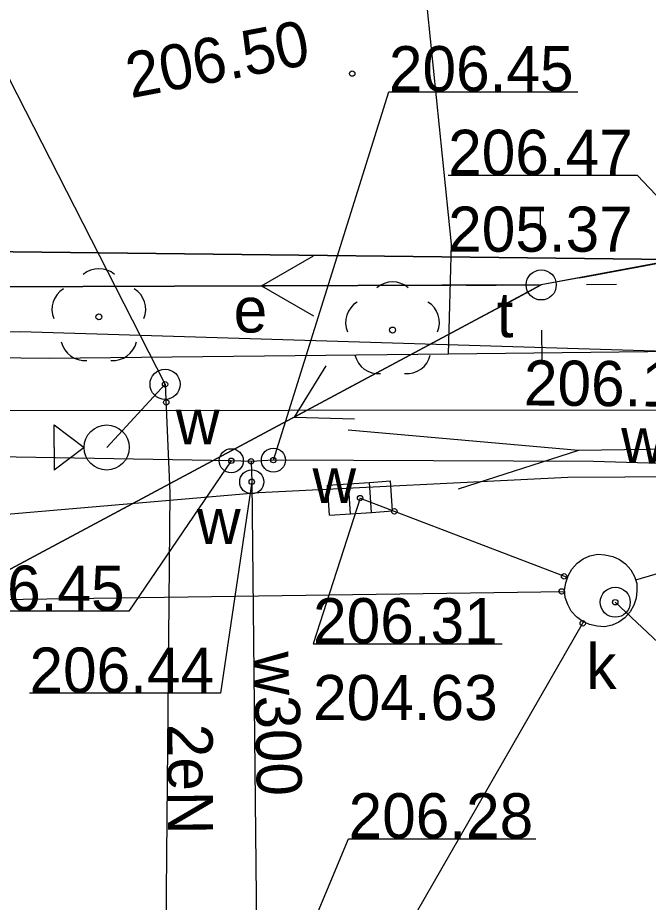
# Model space of a CAD drawing. Extents: x 6512606 to 6513347, y 6022524 to 6022728.
# Drawn here: x 6512773.39 to 6512783.87, y 6022679.43 to 6022694.12 of the extents above; entities that cross this region are included whole.
import ezdxf

# ---------------------------------------------------------------- set-up
doc = ezdxf.new("R2010")
doc.units = 0
for name, color, linetype in [('218-kontur użytku gruntowego', 7, 'Continuous'), ('219-działka ewidencyjna', 7, 'Continuous'), ('4', 7, 'Continuous'), ('chodnik (powierzchnia)', 7, 'Continuous'), ('Default', 7, 'Continuous'), ('drzewo liściaste (punkt)', 7, 'Continuous'), ('inna obudowa przewodu - sieć elektroenergetyczna (linia)', 7, 'Continuous'), ('komora podziemna - przewód kanalizacyjny (powierzchnia)', 7, 'Continuous'), ('kratka ściekowa (punkt)', 7, 'Continuous'), ('krawężnik (linia)', 7, 'Continuous'), ('latarnia na słupie lub maszcie (punkt)', 7, 'Continuous'), ('przewód elektroenergetyczny (linia)', 7, 'Continuous'), ('przewód elektroenergetyczny (linia)-Atr1', 7, 'Continuous'), ('przewód elektroenergetyczny niskiego napięcia (linia)', 7, 'Continuous'), ('przewód elektroenergetyczny niskiego napięcia (linia) - symbol', 7, 'Continuous'), ('przewód gazowy (linia)', 7, 'Continuous'), ('przewód kanalizacyjny (linia)', 7, 'Continuous'), ('przewód telekomunikacyjny (linia)', 7, 'Continuous'), ('przewód wodociągowy (linia)', 7, 'Continuous'), ('przewód wodociągowy (linia)-Atr1', 7, 'Continuous'), ('punkt o określonej wysokości (sieć elektroenergetyczna)', 7, 'Continuous'), ('punkt o określonej wysokości (sieć elektroenergetyczna)-Atr2', 7, 'Continuous'), ('punkt o określonej wysokości (sieć kanalizacyjna)', 7, 'Continuous'), ('punkt o określonej wysokości (sieć kanalizacyjna)-Atr2', 7, 'Continuous'), ('punkt o określonej wysokości (sieć kanalizacyjna)-Atr3', 7, 'Continuous'), ('punkt o określonej wysokości (sieć telekomunikacyjna)-Atr2', 7, 'Continuous'), ('punkt o określonej wysokości (sieć telekomunikacyjna)-Atr3', 7, 'Continuous'), ('punkt o określonej wysokości (sieć wodociągowa)', 7, 'Continuous'), ('punkt o określonej wysokości (sieć wodociągowa)-Atr2', 7, 'Continuous'), ('punkt wysokościowy sztuczny', 7, 'Continuous'), ('punkt wysokościowy sztuczny-Atr2', 7, 'Continuous'), ('sygnalizator świetlny (punkt)', 7, 'Continuous'), ('właz okrągły - siec elektroenergetyczna (punkt)', 7, 'Continuous'), ('właz okrągły - siec elektroenergetyczna (punkt)-Atr17', 7, 'Continuous'), ('właz okrągły - siec kanalizacyjna (punkt)', 7, 'Continuous'), ('właz okrągły - siec kanalizacyjna (punkt)-Atr17', 7, 'Continuous'), ('właz okrągły - siec telekomunikacyjna (punkt)', 7, 'Continuous'), ('właz okrągły - siec telekomunikacyjna (punkt)-Atr17', 7, 'Continuous'), ('zasuwa - siec wodociągowa (punkt)', 7, 'Continuous'), ('zasuwa - siec wodociągowa (punkt)-Atr17', 7, 'Continuous')]:
    doc.layers.add(name, color=color, linetype=linetype)

# ---------------------------------------------------------------- blocks, each defined once
blk = doc.blocks.new('OP021')
at = {"layer": 'Default'}
blk.add_circle((0, 0), 0.5, dxfattribs=at)
for centre, start, end in [((0, 4), 49.272, 130.728), ((-3.8, 1.24), 121.308, 202.548), ((3.8, 1.24), 337.452, 58.692), ((-2.35, -3.24), 193.221, 274.871), ((2.35, -3.24), 265.129, 346.779)]:
    blk.add_arc(centre, 4, start, end, dxfattribs=at)
blk = doc.blocks.new('PE04')
at = {"layer": 'Default'}
for p, q in [((46.5, 0), (37.84, 5)), ((6.5, 0), (0, 0)), ((6.5, 0), (16.5, 0)), ((16.5, 0), (26.5, 0)), ((26.5, 0), (36.5, 0)), ((36.5, 0), (46.5, 0)), ((46.5, 0), (37.84, -5)), ((46.5, 0), (50, 0))]:
    blk.add_line(p, q, dxfattribs=at)
blk = doc.blocks.new('SM011')
at = {"layer": 'Default'}
for p, q in [((-5.3, 5.31), (-8.83, 8.84)), ((5.31, 5.31), (8.84, 8.84)), ((-5.3, -5.3), (-8.83, -8.83)), ((5.31, -5.3), (8.84, -8.83))]:
    blk.add_line(p, q, dxfattribs=at)
blk = doc.blocks.new('US22')
at = {"layer": 'Default'}
blk.add_circle((0, 0), 2.5, dxfattribs=at)
blk = doc.blocks.new('PW02')
at = {"layer": 'Default'}
blk.add_circle((0, 0), 0.45, dxfattribs=at)
blk = doc.blocks.new('PW01')
at = {"layer": 'Default'}
blk.add_circle((0, 0), 0.45, dxfattribs=at)
blk = doc.blocks.new('US25')
at = {"layer": 'Default'}
blk.add_circle((0, 0), 2, dxfattribs=at)
blk = doc.blocks.new('US05')
at = {"layer": 'Default'}
for p, q in [((-5.25, -2.5), (-5.25, 2.5)), ((-5.25, 2.5), (-1.75, 2.5)), ((-1.75, -2.5), (-1.75, 2.5)), ((-1.75, 2.5), (1.75, 2.5)), ((1.75, -2.5), (1.75, 2.5)), ((1.75, 2.5), (5.25, 2.5)), ((5.25, -2.5), (5.25, 2.5)), ((-5.25, -2.5), (-1.75, -2.5)), ((-1.75, -2.5), (1.75, -2.5)), ((1.75, -2.5), (5.25, -2.5))]:
    blk.add_line(p, q, dxfattribs=at)
blk = doc.blocks.new('US16')
at = {"layer": 'Default'}
for p, q in [((-8.75, 0), (-8.75, 3.75)), ((-8.75, 3.75), (-3.75, 0)), ((-8.75, 0), (-8.75, -3.75)), ((-3.75, 0), (-8.75, -3.75))]:
    blk.add_line(p, q, dxfattribs=at)
blk.add_circle((0, 0), 3.75, dxfattribs=at)

msp = doc.modelspace()

# ---------------------------------------------------------------- linework, layer by layer
at = {"layer": '218-kontur użytku gruntowego'}
for points in [[(6512706.4, 6022691.01), (6512787.08, 6022690.07)], [(6512787.08, 6022690.07), (6512706.4, 6022691.01)]]:
    msp.add_lwpolyline(points, dxfattribs=at)
at = {"layer": '219-działka ewidencyjna'}
msp.add_lwpolyline([(6512706.4, 6022691.01), (6512787.08, 6022690.07)], dxfattribs=at)
at = {"layer": '4'}
msp.add_lwpolyline([(6512706.4, 6022691.01), (6512787.08, 6022690.07)], dxfattribs=at)
at = {"layer": 'chodnik (powierzchnia)'}
for points in [[(6512780.55, 6022688.53), (6512780.6, 6022690.36), (6512779.7, 6022699.13), (6512765.93, 6022701.44), (6512762.734, 6022702.478)], [(6512786.39, 6022689.96), (6512786.43, 6022689.56), (6512785.75, 6022688.59), (6512780.55, 6022688.53), (6512773.92, 6022688.46), (6512772.96, 6022688.47), (6512771.38, 6022688.54), (6512759.61, 6022688.41), (6512758.59, 6022688.29), (6512753.64, 6022688.13), (6512742.85, 6022687.9), (6512740.21, 6022687.75), (6512727.76, 6022687.39)]]:
    msp.add_lwpolyline(points, dxfattribs=at)
at = {"layer": 'inna obudowa przewodu - sieć elektroenergetyczna (linia)'}
msp.add_lwpolyline([(6512775.92, 6022686.23), (6512775.83, 6022676.58), (6512775.83, 6022676.57)], dxfattribs=at)
at = {"layer": 'komora podziemna - przewód kanalizacyjny (powierzchnia)'}
msp.add_lwpolyline([(6512783.68, 6022684.6), (6512783.67, 6022684.48), (6512783.63, 6022684.36), (6512783.57, 6022684.25), (6512783.48, 6022684.15), (6512783.38, 6022684.08), (6512783.27, 6022684.03), (6512783.14, 6022684), (6512783.02, 6022684.01), (6512782.89, 6022684.04), (6512782.78, 6022684.09), (6512782.68, 6022684.16), (6512782.59, 6022684.26), (6512782.53, 6022684.37), (6512782.49, 6022684.49), (6512782.48, 6022684.61), (6512782.5, 6022684.73), (6512782.54, 6022684.85), (6512782.6, 6022684.96), (6512782.69, 6022685.06), (6512782.79, 6022685.13), (6512782.9, 6022685.18), (6512783.03, 6022685.21), (6512783.15, 6022685.2), (6512783.28, 6022685.17), (6512783.39, 6022685.12), (6512783.49, 6022685.05), (6512783.58, 6022684.95), (6512783.64, 6022684.84), (6512783.68, 6022684.72)], close=True, dxfattribs=at)
at = {"layer": 'krawężnik (linia)'}
msp.add_lwpolyline([(6512757.15, 6022684.27), (6512758.69, 6022684.41), (6512769.83, 6022685.51), (6512772.56, 6022685.82), (6512777.4, 6022686.23), (6512782.53, 6022686.49), (6512786.32, 6022686.51), (6512790.79, 6022686.51)], dxfattribs=at)
at = {"layer": 'przewód elektroenergetyczny (linia)'}
for points in [[(6512774.87, 6022686.98), (6512775.84, 6022688.03)], [(6512775.84, 6022688.03), (6512775.92, 6022686.23), (6512775.83, 6022676.58), (6512776, 6022676.02)], [(6512782.71, 6022686.93), (6512778.88, 6022687.27)], [(6512827.998, 6022686.723), (6512793.03, 6022687.08), (6512782.71, 6022686.93), (6512780.71, 6022686.29)]]:
    msp.add_lwpolyline(points, dxfattribs=at)
at = {"layer": 'przewód elektroenergetyczny niskiego napięcia (linia)'}
for points in [[(6512803.27, 6022693.63), (6512782.09, 6022689.68)], [(6512782.09, 6022689.68), (6512702.887, 6022689.392)], [(6512702.887, 6022689.392), (6512782.09, 6022689.68)], [(6512751.03, 6022673.06), (6512782.09, 6022689.68)], [(6512782.09, 6022689.68), (6512751.03, 6022673.06)]]:
    msp.add_lwpolyline(points, dxfattribs=at)
at = {"layer": 'przewód gazowy (linia)'}
msp.add_lwpolyline([(6512790.27, 6022690.86), (6512788.32, 6022687.6), (6512767.44, 6022687.59), (6512763.53, 6022687.67), (6512763.38, 6022691.72), (6512760.4, 6022692.03), (6512740.79, 6022692.33), (6512723.64, 6022692.06), (6512711.62, 6022691.95), (6512703.17, 6022690.39), (6512702.97, 6022685.4), (6512702.78, 6022684.183)], dxfattribs=at)
at = {"layer": 'przewód kanalizacyjny (linia)'}
for points in [[(6512783.66, 6022684.78), (6512794.77, 6022688.03)], [(6512779.08, 6022686.14), (6512782.53, 6022684.82)], [(6512749.24, 6022684.12), (6512782.48, 6022684.59)], [(6512782.79, 6022684.08), (6512778.69, 6022676.95)]]:
    msp.add_lwpolyline(points, dxfattribs=at)
at = {"layer": 'przewód telekomunikacyjny (linia)'}
msp.add_lwpolyline([(6512786.53, 6022688.5), (6512773.43, 6022688.9), (6512751.33, 6022688.79), (6512741.32, 6022689.08), (6512718.97, 6022688.75), (6512713.12, 6022690.07), (6512711.25, 6022690.1), (6512706.82, 6022689.08), (6512704.98, 6022689.07)], dxfattribs=at)
at = {"layer": 'przewód wodociągowy (linia)'}
for points in [[(6512805.45, 6022688.13), (6512805.12, 6022688.1), (6512792.38, 6022686.88), (6512788.46, 6022686.58), (6512782.96, 6022686.75), (6512777.64, 6022686.77), (6512777.27, 6022686.75)], [(6512777.27, 6022686.75), (6512776.94, 6022686.76), (6512762.32, 6022687.01), (6512742.89, 6022685.83), (6512741.87, 6022684.29)], [(6512777.27, 6022686.75), (6512777.28, 6022686.41), (6512777.38, 6022676.87), (6512777.41, 6022676.47)]]:
    msp.add_lwpolyline(points, dxfattribs=at)
at = {"layer": 'punkt o określonej wysokości (sieć elektroenergetyczna)-Atr2'}
msp.add_lwpolyline([(6512775.84, 6022688.03), (6512772.7, 6022694.17), (6512769.559, 6022694.17)], dxfattribs=at)
at = {"layer": 'punkt o określonej wysokości (sieć kanalizacyjna)-Atr2'}
for points in [[(6512779.08, 6022686.14), (6512778.3, 6022683.72), (6512781.441, 6022683.72)], [(6512783.32, 6022684.41), (6512784.84, 6022682.98), (6512787.949, 6022682.98)]]:
    msp.add_lwpolyline(points, dxfattribs=at)
at = {"layer": 'punkt o określonej wysokości (sieć telekomunikacyjna)-Atr2'}
msp.add_lwpolyline([(6512786.53, 6022688.5), (6512783.69, 6022691.5), (6512780.544, 6022691.5)], dxfattribs=at)
at = {"layer": 'punkt o określonej wysokości (sieć wodociągowa)-Atr2'}
for points in [[(6512777.64, 6022686.77), (6512779.56, 6022692.89), (6512782.701, 6022692.89)], [(6512776.94, 6022686.76), (6512775.24, 6022684.26), (6512772.099, 6022684.26)], [(6512777.28, 6022686.41), (6512776.76, 6022682.9), (6512773.587, 6022682.9)], [(6512777.38, 6022676.87), (6512778.89, 6022680.48), (6512781.999, 6022680.48)]]:
    msp.add_lwpolyline(points, dxfattribs=at)

# ---------------------------------------------------------------- block references
at = {"layer": 'drzewo liściaste (punkt)', "xscale": 0.1, "yscale": 0.10000000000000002}
for p in [(6512774.74, 6022689.15), (6512779.62, 6022688.93)]:
    msp.add_blockref('OP021', p, dxfattribs=at)
at = {"layer": 'kratka ściekowa (punkt)', "xscale": 0.1, "yscale": 0.10000000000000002, "rotation": 3.8569999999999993}
msp.add_blockref('US05', (6512779.08, 6022686.14), dxfattribs=at)
at = {"layer": 'latarnia na słupie lub maszcie (punkt)', "xscale": 0.10000000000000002, "yscale": 0.1, "rotation": 45.573}
msp.add_blockref('SM011', (6512782.09, 6022689.68), dxfattribs=at)
at = {"layer": 'przewód elektroenergetyczny niskiego napięcia (linia) - symbol'}
for xscale, yscale, rotation in [(0.10000000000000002, 0.1, 10.563999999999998), (0.1, 0.09999999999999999, -179.79200000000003), (0.1, 0.09999999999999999, -151.84900000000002)]:
    msp.add_blockref('PE04', (6512782.09, 6022689.68), dxfattribs=dict(at, xscale=xscale, yscale=yscale, rotation=rotation))
at = {"layer": 'punkt o określonej wysokości (sieć elektroenergetyczna)', "yscale": 0.1}
for p, xscale, rotation in [((6512775.84, 6022688.03), 0.09999999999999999, 3.468), ((6512775.86, 6022687.73), 0.10000000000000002, -86.82)]:
    msp.add_blockref('PW01', p, dxfattribs=dict(at, xscale=xscale, rotation=rotation))
at = {"layer": 'punkt o określonej wysokości (sieć kanalizacyjna)'}
for p, xscale, yscale, rotation in [((6512779.08, 6022686.14), 0.1, 0.10000000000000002, 3.8569999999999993), ((6512779.65, 6022685.92), 0.09999999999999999, 0.1, -20.101999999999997), ((6512782.47, 6022684.84), 0.09999999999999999, 0.1, -20.101999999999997), ((6512782.43, 6022684.59), 0.1, 0.10000000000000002, 1.62), ((6512782.78, 6022684.06), 0.10000000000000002, 0.09999999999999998, 60.912)]:
    msp.add_blockref('PW01', p, dxfattribs=dict(at, xscale=xscale, yscale=yscale, rotation=rotation))
at = {"layer": 'punkt o określonej wysokości (sieć kanalizacyjna)', "xscale": 0.1, "yscale": 0.10000000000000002}
msp.add_blockref('PW01', (6512783.32, 6022684.41), dxfattribs=at)
at = {"layer": 'punkt o określonej wysokości (sieć wodociągowa)'}
for p, xscale, yscale, rotation in [((6512776.94, 6022686.76), 0.1, 0.10000000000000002, -1.7350000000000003), ((6512777.64, 6022686.77), 0.09999999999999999, 0.1, 0.5390000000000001), ((6512777.28, 6022686.41), 0.1, 0.09999999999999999, -88.315)]:
    msp.add_blockref('PW01', p, dxfattribs=dict(at, xscale=xscale, yscale=yscale, rotation=rotation))
at = {"layer": 'punkt o określonej wysokości (sieć wodociągowa)', "xscale": 0.1, "yscale": 0.10000000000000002}
msp.add_blockref('PW01', (6512777.27, 6022686.75), dxfattribs=at)
at = {"layer": 'punkt wysokościowy sztuczny', "xscale": 0.1, "yscale": 0.10000000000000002}
msp.add_blockref('PW02', (6512778.95, 6022693.19), dxfattribs=at)
at = {"layer": 'sygnalizator świetlny (punkt)', "xscale": 0.1, "yscale": 0.10000000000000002}
msp.add_blockref('US16', (6512774.87, 6022686.98), dxfattribs=at)
at = {"layer": 'właz okrągły - siec elektroenergetyczna (punkt)', "xscale": 0.09999999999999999, "yscale": 0.1, "rotation": 3.468}
msp.add_blockref('US22', (6512775.84, 6022688.03), dxfattribs=at)
at = {"layer": 'właz okrągły - siec kanalizacyjna (punkt)', "xscale": 0.1, "yscale": 0.10000000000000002}
msp.add_blockref('US22', (6512783.32, 6022684.41), dxfattribs=at)
at = {"layer": 'właz okrągły - siec telekomunikacyjna (punkt)', "xscale": 0.1, "yscale": 0.10000000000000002}
msp.add_blockref('US22', (6512782.09, 6022689.68), dxfattribs=at)
at = {"layer": 'zasuwa - siec wodociągowa (punkt)'}
for p, xscale, yscale, rotation in [((6512776.94, 6022686.76), 0.1, 0.10000000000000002, -1.7350000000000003), ((6512777.64, 6022686.77), 0.09999999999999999, 0.1, 0.5390000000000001), ((6512777.28, 6022686.41), 0.1, 0.09999999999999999, -88.315)]:
    msp.add_blockref('US25', p, dxfattribs=dict(at, xscale=xscale, yscale=yscale, rotation=rotation))

# ---------------------------------------------------------------- texts
at = {"layer": 'przewód elektroenergetyczny (linia)-Atr1'}
msp.add_text('2eN', height=0.75, rotation=270.297, dxfattribs=at).set_placement((6512775.88, 6022682.39))
at = {"layer": 'przewód wodociągowy (linia)-Atr1'}
for s, rotation, p in [('w200', 359.063, (6512783.41, 6022686.73)), ('w300', 271.382, (6512777.31, 6022683.58))]:
    msp.add_text(s, height=0.75, rotation=rotation, dxfattribs=at).set_placement(p)
at = {"layer": 'punkt o określonej wysokości (sieć kanalizacyjna)-Atr2'}
msp.add_text('206.31', height=0.75, dxfattribs=at).set_placement((6512778.3, 6022683.728))
at = {"layer": 'punkt o określonej wysokości (sieć kanalizacyjna)-Atr3'}
msp.add_text('204.63', height=0.75, dxfattribs=at).set_placement((6512778.3, 6022682.452))
at = {"layer": 'punkt o określonej wysokości (sieć telekomunikacyjna)-Atr2'}
msp.add_text('206.47', height=0.75, dxfattribs=at).set_placement((6512780.544, 6022691.508))
msp.add_text('206.15', height=0.75, rotation=359.478, dxfattribs=at).set_placement((6512781.8, 6022687.68))
at = {"layer": 'punkt o określonej wysokości (sieć telekomunikacyjna)-Atr3'}
msp.add_text('205.37', height=0.75, dxfattribs=at).set_placement((6512780.544, 6022690.232))
at = {"layer": 'punkt o określonej wysokości (sieć wodociągowa)-Atr2'}
for s, p in [('206.45', (6512779.56, 6022692.897)), ('206.45', (6512772.099, 6022684.268)), ('206.44', (6512773.587, 6022682.908)), ('206.28', (6512778.89, 6022680.488))]:
    msp.add_text(s, height=0.75, dxfattribs=at).set_placement(p)
at = {"layer": 'punkt wysokościowy sztuczny-Atr2'}
msp.add_text('206.50', height=0.75, rotation=10.741, dxfattribs=at).set_placement((6512775.27, 6022692.78))
at = {"layer": 'właz okrągły - siec elektroenergetyczna (punkt)-Atr17'}
msp.add_text('e', height=0.75, dxfattribs=at).set_placement((6512776.98, 6022688.89))
at = {"layer": 'właz okrągły - siec kanalizacyjna (punkt)-Atr17'}
msp.add_text('k', height=0.75, dxfattribs=at).set_placement((6512782.84, 6022682.97))
at = {"layer": 'właz okrągły - siec telekomunikacyjna (punkt)-Atr17'}
msp.add_text('t', height=0.75, dxfattribs=at).set_placement((6512781.35, 6022688.81))
at = {"layer": 'zasuwa - siec wodociągowa (punkt)-Atr17'}
for p in [(6512776.02, 6022687.03), (6512778.29, 6022686.06), (6512776.37, 6022685.38)]:
    msp.add_text('w', height=0.75, dxfattribs=at).set_placement(p)

doc.saveas('drawing.dxf')
